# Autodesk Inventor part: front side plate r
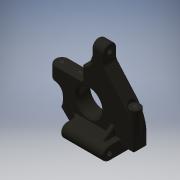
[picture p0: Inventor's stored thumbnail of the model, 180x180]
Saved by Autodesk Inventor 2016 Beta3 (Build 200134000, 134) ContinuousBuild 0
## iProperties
Shininess: 41.0
Compacted: True
Length Units: 11272
Angle Units: 11279
Time Units: 11290
Mass Units: 11286
Length Display Precision: 3
Angle Display Precision: 2
Company: Autodesk
Created: 2001-02
Part Number: front side plate r
Document SubType Name: Modeling
Designer: Autodesk, Inc.
Project: Inventor Samples
Density: 1.28 g/cm^3
Stock Number: front side plate r
Material: Stiffzel
Mass: 15.7207 g
Surface Area: 55.8097 cm^2
Volume: 12.2818 cm^3
Appearance: Stiffzel
Density: 0.0
Volumn: 0.0
Area: 0.0
PropertySet Name: Model Information
Control State: 0
Master: False
Checked Out: False
Author: Autodesk, Inc.
Revision Number: A
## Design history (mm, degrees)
sketch "Sketch1"
  geometry: L1 (-34.263, -17.296)-(16.537, -17.296); L2 (16.537, -17.296)-(16.537, -6.501); L3 (-8.584, 18.544)-(-13.878, 9.374); L4 (-13.878, 9.374)-(-34.263, 9.374); L5 (-34.263, 9.374)-(-34.263, 0.865); L6 (-34.263, 0.865)-(-26.262, 0.865); L7 (-26.262, 0.865)-(-26.262, -11.835); L8 (-26.262, -11.835)-(-34.263, -11.835); L9 (-34.263, -11.835)-(-34.263, -17.296); L10 (10.258, 10.218)-(-1.567, 23.743); L11 (-8.584, 18.544)-(-8.584, 29.059); L12 (-8.584, 29.059)-(-1.567, 29.059); L13 (-1.567, 29.059)-(-1.567, 23.743); A1 r 25.4 centre (-8.863, -6.501) between (16.537, -6.501) and (10.258, 10.218)
  constraints: 26 end point, 6 parallel, 3 perpendicular, 2 point on circle, 2 tangent, 1 centre point, 1 collinear, 1 horizontal, 1 vertical alignment, 1 other
  dimensions: "d0" = 5.461 distance of L8.end L1.start; "d1" = 50.8 distance of L1.start L1.end; "d2" = 25.4 radius of A1; "d5" = 10.795 distance from line of L1 A1.centre; "d7" = 26.67 distance between parallel lines of L1 L4; "d8" = 120 deg angle of L4 L3; "d9" = 8.001 distance between parallel lines of L9 L7; "d10" = 12.7 distance of L6.end L7.end; "d186" = 48.8349 deg angle of L1 L10; "d187" = 25.1207 distance from line of L2 L3.start; "d188" = 7.01675 distance between parallel lines of L13 L11; "d189" = 46.355 distance between parallel lines of L1 L12; "d191" = 9.17024 vertical distance of L3.start L3.end
extrude "Extrusion1" new body sketch "Sketch1" distance "d13" = 8.001; taper "d14" = 0 deg
sketch "Sketch2"
  geometry: L1 (16.537, -17.296)-(-34.263, -17.296) reference; L2 (16.537, -17.296)-(8.536, -17.296); L3 (8.536, -17.296)-(8.536, -12.534); L4 (8.536, -12.534)-(16.537, -12.534); L5 (16.537, -12.534)-(16.537, -17.296)
  constraints: 8 end point, 2 parallel, 1 horizontal, 1 perpendicular
  dimensions: "d15" = 4.7625 distance between parallel lines of L1 L4; "d184" = 8.001 distance between parallel lines of L5 L3
extrude "Extrusion2" cut sketch "Sketch2" stored distance "d16" = 6.35; taper "d17" = 0 deg
fillet "Fillet1" dims "d18" = 4.0005 (= 0.5 x d13)
sketch "Sketch10"
  geometry: L1 (39.026, 1.373)-(34.263, 9.374) reference; L2 (34.263, 9.374)-(13.878, 9.374) reference; L3 (13.878, 9.374)-(2.513, 29.059) reference; L4 (31.088, 0.865)-(24.675, 0.865) reference; L5 (8.838, 18.105)-(14.07, 18.105); L6 (14.07, 18.105)-(14.07, 9.374)
  constraints: 4 end point, 2 point on line, 1 parallel, 1 perpendicular
  dimensions: "d62" = 8.73125 distance between parallel lines of L5 L2; "d63" = 20.193 distance between parallel lines of L1 L6
extrude "Extrusion9" join sketch "Sketch10" stored distance "d64" = 4.7625; taper "d65" = 0 deg
sketch "Sketch28"
  geometry: L1 (0, 5.316)-(-8.001, 5.316) reference; 1 further point
  constraints: 1 horizontal alignment, 1 midpoint, 2 other
extrude "Extrusion19" join sketch "Sketch28" stored distance "d192" = 25.4; taper "d193" = 0 deg
sketch "Sketch29"
  geometry: L1 (-30.263, 0.865)-(-30.263, 9.374) reference; L2 (-26.262, 0.865)-(-30.263, 0.865) reference; L3 (-26.262, -11.835)-(-26.262, 0.865) reference; L4 (-30.263, -11.835)-(-26.262, -11.835) reference; L5 (-30.263, -17.296)-(-30.263, -11.835) reference; L6 (8.536, -17.296)-(-30.263, -17.296) reference; L7 (8.536, -17.296)-(8.536, -12.534) reference; L8 (8.536, -12.534)-(16.537, -12.534) reference; L9 (16.537, -6.501)-(16.537, -12.534) reference; L10 (-1.567, 23.743)-(10.258, 10.218) reference; L11 (-1.567, 29.059)-(-1.567, 23.743) reference; L12 (-8.584, 29.059)-(-1.567, 29.059) reference; L13 (-8.584, 18.544)-(-8.584, 29.059) reference; L14 (-8.838, 18.105)-(-8.584, 18.544) reference; L15 (-14.07, 18.105)-(-8.838, 18.105) reference; L16 (-14.07, 9.374)-(-14.07, 18.105) reference; L17 (-30.263, 9.374)-(-14.07, 9.374) reference; A1 r 25.4 centre (-8.863, -6.501) between (16.537, -6.501) and (10.258, 10.218) reference; A2 r 5.486 centre (-14.07, 23.591) between (-14.07, 18.105) and (-8.584, 23.591)
  constraints: 3 point on line, 2 point on circle, 2 tangent, 1 centre point
extrude "Extrusion20" join sketch "Sketch29" stored distance "d194" = 25.4; taper "d195" = 0 deg
sketch "Sketch4"
  geometry: L1 (-16.537, -6.501)-(-16.537, -12.534) reference; L2 (-8.536, -17.296)-(30.263, -17.296) reference; C1 r 9.525 at (10.451, 0.039)
  constraints: 1 centre point
  dimensions: "d30" = 17.3355 distance from line of C1.centre L2; "d31" = 19.05 diameter of C1; "d32" = 26.9875 distance from line of C1.centre L1
extrude "Extrusion4" join sketch "Sketch4" distance "d33" = 0.889; taper "d34" = 0 deg
fillet "Fillet12" dims "d49" = 0.8128
sketch "Sketch6"
  geometry: C1 r 9.525 at (0, 0) reference; C2 r 7.938 at (0, 0)
  constraints: 1 centre point, 1 coincident
  dimensions: "d50" = 15.875 diameter of C2
extrude "Extrusion6" cut sketch "Sketch6" distance "d51" = 3.27152; taper "d52" = 0 deg
sketch "Sketch7"
  geometry: C1 r 9.525 at (0, 0) reference; C2 r 6.985 at (0, 0)
  constraints: 1 centre point, 1 coincident
  dimensions: "d53" = 13.97 diameter of C2
extrude "Extrusion7" cut sketch "Sketch7" stored distance "d54" = 3.27152; taper "d55" = 0 deg
chamfer "Chamfer2" distance "d56" = 1.27; stored, may be unused: second distance "d57" = 1.27, angle "d250" = 45 deg
fillet "Fillet43" dims "d115" = 4.7625
fillet "Fillet44" dims "d116" = 0.8128
fillet "Fillet45" dims "d117" = 0.8128
fillet "Fillet64" dims "d196" = 3.175
fillet "Fillet46" dims "d118" = 0.8128
fillet "Fillet47" dims "d119" = 0.8128
fillet "Fillet48" dims "d120" = 0.381
fillet "Fillet49" dims "d121" = 0.8128
workplane "Work Plane1"
workplane "Work Plane2"
workplane "Work Plane3"
workplane "Work Plane4"
workpoint "Work Point3"
workaxis "Work Axis1"
workplane "Work Plane5"
sketch "Sketch20"
  geometry: L1 (-11.23, 0)-(-6.468, 0) reference; L2 (-11.23, 6.35)-(-11.23, 0); L3 (-3.229, 6.35)-(-3.229, 0); L4 (-3.229, 0)-(-11.23, 0); A1 r 4.001 centre (-7.23, 6.35) between (-11.23, 6.35) and (-3.229, 6.35); 1 further point
  constraints: 6 end point, 2 perpendicular, 2 point on circle, 2 point on line, 2 tangent, 1 centre point, 1 coincident, 1 collinear
  dimensions: "d128" = 8.001 diameter of A1
extrude "Extrusion16" join sketch "Sketch20" stored distance "d129" = 25.4; taper "d130" = 0 deg
fillet "Fillet50" dims "d131" = 0.8128
fillet "Fillet51" dims "d132" = 0.8128
fillet "Fillet52" dims "d133" = 3.175
fillet "Fillet53" dims "d134" = 0.8128
fillet "Fillet54" dims "d135" = 0.8128
fillet "Fillet55" dims "d136" = 0.8128
fillet "Fillet56" dims "d137" = 0.381
sketch "Sketch21"
  geometry: 3 further points
  constraints: 1 other
hole "Hole1" sketch "Sketch21" at (-6.35, -7.23) diameter "d138" = 3.175; stored, may be unused: countersink angle "d142" = 60 deg, drill point angle "d144" = 118 deg; dims "d139" = 12.7, "d140" = 9.525, "d141" = 6.35, "d143" = 19.05
workplane "Work Plane6"
sketch "Sketch22"
  geometry: L1 (-7.166, -2.119)-(-1.617, 1.958)
  constraints: 2 end point
feature "Rib1" sketch "Sketch22" dims "d146" = 2.54, "d147" = 2.54
fillet "Fillet57" dims "d148" = 0.8128
fillet "Fillet58" dims "d149" = 0.8128
workplane "Work Plane7"
sketch "Sketch23" dims "d151" = 6.35
  geometry: L1 (46.799, 0)-(46.799, 6.375) reference; L2 (46.799, 3.188)-(32.274, 3.188); 1 further point
  constraints: 2 end point, 1 horizontal alignment, 1 midpoint, 1 perpendicular, 1 point on line, 2 other
extrude "Extrusion17" join sketch "Sketch23" stored distance "d152" = 25.4; taper "d153" = 0 deg
sketch "Sketch24"
  geometry: C1 r 3.175 at (43.624, -3.188); A1 r 3.175 centre (43.624, -3.188) between (42.181, -6.015) and (42.181, -0.36) reference
  constraints: 1 centre point, 1 coincident
  dimensions: "d154" = 6.35 diameter of C1
extrude "Extrusion18" cut sketch "Sketch24" stored distance "d155" = 25.4; taper "d156" = 0 deg
fillet "Fillet60" dims "d158" = 0.381
fillet "Fillet62" dims "d160" = 0.381
fillet "Fillet63" dims "d161" = 0.381
sketch "Sketch25"
  geometry: A1 r 2.794 centre (43.624, -3.188) between (43.987, -5.958) and (43.987, -0.417) reference
hole "Hole2" sketch "Sketch25" at (43.624, -3.188) diameter "d162" = 2.159; stored, may be unused: countersink angle "d166" = 60 deg, drill point angle "d168" = 118 deg; dims "d163" = 12.7, "d164" = 9.525, "d165" = 6.35, "d167" = 8.001
workplane "Work Plane8"
sketch "Sketch30"
  geometry: L1 (-29.257, 30.422)-(-25.239, 41.396); A1 r 0.813 centre (-29.794, 29.066) between (-29.899, 29.872) and (-30.607, 29.066) reference; A2 r 0.813 centre (-24.308, 43.967) between (-24.308, 44.78) and (-25.121, 43.967) reference
  constraints: 2 end point
feature "Rib2" sketch "Sketch30" dims "d197" = 2.54, "d198" = 2.54
fillet "Fillet65" dims "d199" = 0.8128
fillet "Fillet66" dims "d200" = 0.8128
sketch "Sketch32"
  geometry: C1 r 2.794 at (-3.188, 5.467); A1 r 3.188 centre (-3.188, 5.467) between (0, 5.467) and (-6.375, 5.467) reference
  constraints: 1 centre point, 1 coincident
  dimensions: "d210" = 5.588 diameter of C1
extrude "Extrusion22" cut sketch "Sketch32" stored distance "d211" = 1.5875; taper "d212" = 0 deg
sketch "Sketch33"
  geometry: A1 r 2.794 centre (-3.188, 5.467) between (-5.166, 3.494) and (-1.21, 3.494) reference; 1 further point
  constraints: 1 coincident, 3 other
extrude "Extrusion23" cut sketch "Sketch33" distance "d213" = 3.81; taper "d214" = 0 deg
fillet "Fillet69" dims "d215" = 0.381
sketch "Sketch34"
  geometry: C1 r 2.794 at (0, 0) reference
hole "Hole5" sketch "Sketch34" at (0, 0) diameter "d216" = 3.175; stored, may be unused: countersink angle "d220" = 60 deg, drill point angle "d222" = 118 deg; dims "d217" = 12.7, "d218" = 9.525, "d219" = 6.35, "d221" = 19.05
sketch "Sketch35"
  geometry: C1 r 1.587 at (0, -3.188); C2 r 1.587 at (11.049, -3.188); A1 r 3.188 centre (0, -3.188) between (0, 0) and (0, -6.375) reference
  constraints: 2 centre point, 1 concentric, 1 horizontal alignment
  dimensions: "d223" = 11.049 distance of C2.centre A1.centre
hole "Hole6" sketch "Sketch35" at (0, -3.188), (11.049, -3.188) diameter "d224" = 2.159; stored, may be unused: countersink angle "d228" = 60 deg, drill point angle "d230" = 118 deg; dims "d225" = 12.7, "d226" = 9.525, "d227" = 6.35, "d229" = 8.001
body "Solid1"
other parameters: "d123" = -10 deg, "d124" = 0, "d125" = 6.35, "d126" = -4.0005, "d127" = -25.4, "d145" = -12.7, "d150" = -25.4, "d190" = 25.1207 (derived)
